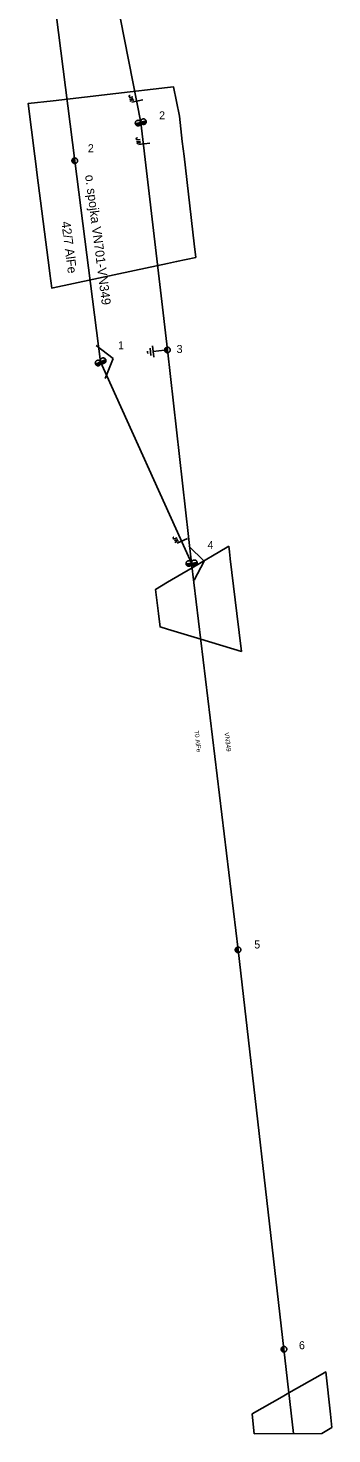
# Model space of a CAD drawing. Extents: x -536397 to -535454, y -1201642 to -1200953.
# Drawn here: x -536243 to -536176.6, y -1201641.8 to -1201334.5 of the extents above; entities that cross this region are included whole.
import ezdxf

# ---------------------------------------------------------------- set-up
doc = ezdxf.new("R2010")
doc.units = 0
for name, color, linetype in [('DOPLŇ_POPISY', 7, 'Continuous'), ('ELE_EON', 7, 'Continuous'), ('ELE_EON_POPIS', 7, 'Continuous'), ('KN_HRAN_POHYBLIVÁ', 7, 'Continuous'), ('PB_NN', 7, 'Continuous'), ('PB_NN_POPIS', 7, 'Continuous'), ('PK_HRAN_SPORNÁ', 7, 'Continuous'), ('PLG_EXPORT_GPE', 7, 'Continuous'), ('PODZEM_NN_POPIS', 7, 'Continuous'), ('RÁMEČEK', 7, 'Continuous'), ('SDEL_EON', 7, 'Continuous')]:
    doc.layers.add(name, color=color, linetype=linetype)

# ---------------------------------------------------------------- blocks, each defined once
blk = doc.blocks.new('VN840')
at = {"layer": 'RÁMEČEK'}
for points in [[(-0.01, 1.41), (-0.01, -1.09)], [(-1.51, -1.24), (-1.51, -1.15)], [(-1.48, -1.35), (-1.51, -1.24)], [(-1.33, -1.42), (-1.48, -1.35)], [(-1.27, -1.42), (-1.33, -1.42)], [(-1.13, -1.35), (-1.27, -1.42)], [(-1.09, -1.24), (-1.13, -1.35)], [(-1.09, -0.59), (-1.09, -1.24)], [(-0.68, -0.59), (-0.68, -1.42)], [(-0.68, -1.11), (-0.27, -0.59)], [(-0.54, -0.94), (-0.2, -1.42)]]:
    blk.add_lwpolyline(points, dxfattribs=at)
blk = doc.blocks.new('VN860')
at = {"layer": 'RÁMEČEK'}
for points in [[(-3.74, 0), (0.01, 2.82)], [(0.01, 2.82), (3.76, 0)]]:
    blk.add_lwpolyline(points, dxfattribs=at)
blk = doc.blocks.new('VN440')
at = {"layer": 'ELE_EON_POPIS'}
for points in [[(1.22, 0), (1.21, 0.13), (1.19, 0.25), (1.16, 0.38), (1.11, 0.5), (1.05, 0.61), (0.98, 0.72), (0.9, 0.82), (0.81, 0.91), (0.71, 0.99), (0.6, 1.06), (0.49, 1.12), (0.37, 1.16), (0.25, 1.2), (0.12, 1.22), (-0.01, 1.22), (-0.14, 1.22), (-0.26, 1.2), (-0.39, 1.16), (-0.51, 1.12), (-0.62, 1.06), (-0.73, 0.99), (-0.83, 0.91), (-0.92, 0.82), (-1, 0.72), (-1.07, 0.61), (-1.13, 0.5), (-1.18, 0.38), (-1.21, 0.25), (-1.23, 0.13), (-1.24, 0), (-1.23, -0.13), (-1.21, -0.26), (-1.18, -0.38), (-1.13, -0.5), (-1.07, -0.62), (-1, -0.73), (-0.92, -0.83), (-0.83, -0.92), (-0.73, -1), (-0.62, -1.07), (-0.51, -1.13), (-0.39, -1.17), (-0.26, -1.2), (-0.14, -1.23), (-0.01, -1.23), (0.12, -1.23), (0.25, -1.2), (0.37, -1.17), (0.49, -1.13), (0.6, -1.07), (0.71, -1), (0.81, -0.92), (0.9, -0.83), (0.98, -0.73), (1.05, -0.62), (1.11, -0.5), (1.16, -0.38), (1.19, -0.26), (1.21, -0.13), (1.22, 0)], [(-1.24, 0), (1.22, 0)], [(-1.18, -0.34), (1.1, -0.34)], [(-1.01, -0.63), (0.97, -0.63)], [(-0.74, -0.92), (0.68, -0.92)]]:
    blk.add_lwpolyline(points, dxfattribs=at)
blk = doc.blocks.new('VN810')
at = {"layer": 'PLG_EXPORT_GPE'}
for points in [[(0, -1.25), (0, -3.75)], [(1.25, -3.75), (-1.25, -3.75)], [(0.77, -4.37), (-0.8, -4.37)], [(0, -5), (-0.25, -5)], [(0.27, -5), (0, -5)]]:
    blk.add_lwpolyline(points, dxfattribs=at)
blk = doc.blocks.new('VN450')
at = {"layer": 'ELE_EON_POPIS'}
for points in [[(0, 0), (-0.01, 0.13), (-0.03, 0.25), (-0.06, 0.38), (-0.11, 0.5), (-0.16, 0.61), (-0.23, 0.72), (-0.31, 0.82), (-0.4, 0.91), (-0.5, 0.99), (-0.61, 1.06), (-0.72, 1.11), (-0.84, 1.16), (-0.97, 1.19), (-1.09, 1.21), (-1.22, 1.22), (-1.35, 1.21), (-1.47, 1.19), (-1.59, 1.16), (-1.71, 1.11), (-1.83, 1.06), (-1.93, 0.99), (-2.03, 0.91), (-2.12, 0.82), (-2.2, 0.72), (-2.27, 0.61), (-2.33, 0.5), (-2.38, 0.38), (-2.41, 0.25), (-2.43, 0.13), (-2.44, 0), (-2.43, -0.13), (-2.41, -0.25), (-2.38, -0.38), (-2.33, -0.5), (-2.27, -0.61), (-2.2, -0.72), (-2.12, -0.82), (-2.03, -0.91), (-1.93, -0.99), (-1.83, -1.06), (-1.71, -1.11), (-1.59, -1.16), (-1.47, -1.19), (-1.35, -1.21), (-1.22, -1.22), (-1.09, -1.21), (-0.97, -1.19), (-0.84, -1.16), (-0.72, -1.11), (-0.61, -1.06), (-0.5, -0.99), (-0.4, -0.91), (-0.31, -0.82), (-0.23, -0.72), (-0.16, -0.61), (-0.11, -0.5), (-0.06, -0.38), (-0.03, -0.25), (-0.01, -0.13), (0, 0)], [(-2.44, 0), (2.44, 0)], [(2.44, 0), (2.43, 0.13), (2.41, 0.25), (2.38, 0.38), (2.33, 0.5), (2.27, 0.61), (2.2, 0.72), (2.12, 0.82), (2.03, 0.91), (1.94, 0.99), (1.83, 1.06), (1.71, 1.11), (1.6, 1.16), (1.47, 1.19), (1.35, 1.21), (1.22, 1.22), (1.09, 1.21), (0.97, 1.19), (0.84, 1.16), (0.72, 1.11), (0.61, 1.06), (0.5, 0.99), (0.4, 0.91), (0.31, 0.82), (0.23, 0.72), (0.16, 0.61), (0.11, 0.5), (0.06, 0.38), (0.03, 0.25), (0.01, 0.13), (0, 0), (0.01, -0.13), (0.03, -0.25), (0.06, -0.38), (0.11, -0.5), (0.16, -0.61), (0.23, -0.72), (0.31, -0.82), (0.4, -0.91), (0.5, -0.99), (0.61, -1.06), (0.72, -1.11), (0.84, -1.16), (0.97, -1.19), (1.09, -1.21), (1.22, -1.22), (1.35, -1.21), (1.47, -1.19), (1.6, -1.16), (1.71, -1.11), (1.83, -1.06), (1.94, -0.99), (2.03, -0.91), (2.12, -0.82), (2.2, -0.72), (2.27, -0.61), (2.33, -0.5), (2.38, -0.38), (2.41, -0.25), (2.43, -0.13), (2.44, 0)], [(-2.4, -0.31), (-0.04, -0.31)], [(-2.26, -0.61), (-0.17, -0.61)], [(-2.01, -0.92), (-0.42, -0.92)], [(0.04, -0.31), (2.4, -0.31)], [(0.17, -0.61), (2.27, -0.61)], [(0.42, -0.92), (2.02, -0.92)]]:
    blk.add_lwpolyline(points, dxfattribs=at)

msp = doc.modelspace()

# ---------------------------------------------------------------- linework, layer by layer
at = {"layer": 'ELE_EON'}
for points in [[(-536229.86, -1201296.57), (-536218.36, -1201355.13), (-536212.54, -1201404.88), (-536207.27, -1201451.49)], [(-536207.27, -1201451.49), (-536197.12, -1201536.02), (-536187.09, -1201623.35), (-536185.03, -1201641.79)]]:
    msp.add_lwpolyline(points, dxfattribs=at)
at = {"layer": 'PK_HRAN_SPORNÁ'}
for points in [[(-536223.8, -1201348.8), (-536212.5, -1201347.49), (-536211.24, -1201347.33), (-536209.94, -1201353.78), (-536209.3, -1201359.3), (-536208.92, -1201362.5), (-536206.69, -1201381.69), (-536206.34, -1201384.65), (-536210.55, -1201385.55), (-536212.5, -1201385.96), (-536219.72, -1201387.5), (-536237.5, -1201391.29), (-536237.79, -1201391.34), (-536238.2, -1201388.2), (-536238.29, -1201387.5), (-536241.06, -1201366.06), (-536241.22, -1201364.8), (-536241.51, -1201362.5), (-536242.96, -1201351.03), (-536237.5, -1201350.39)], [(-536199.14, -1201447.78), (-536199, -1201449), (-536198.83, -1201450.48), (-536198.83, -1201450.51), (-536198.82, -1201450.53), (-536197.38, -1201462.5), (-536196.39, -1201470.78), (-536205.28, -1201468.1), (-536212.5, -1201465.93), (-536214.16, -1201465.43), (-536214.3, -1201464.3), (-536214.51, -1201462.5), (-536215.14, -1201457.24), (-536212.5, -1201455.68), (-536207.15, -1201452.51), (-536199.52, -1201448.01)], [(-536193.58, -1201641.85), (-536194.07, -1201637.5), (-536194.07, -1201637.47), (-536187.5, -1201633.73), (-536186.03, -1201632.89), (-536178.71, -1201628.71), (-536177.98, -1201628.3), (-536176.96, -1201637.5), (-536176.63, -1201640.42), (-536178.82, -1201641.75)]]:
    msp.add_lwpolyline(points, close=True, dxfattribs=at)
at = {"layer": 'PODZEM_NN_POPIS'}
msp.add_lwpolyline([(-536238.86, -1201315.34), (-536232.78, -1201363.5), (-536227.13, -1201407.48), (-536207.27, -1201451.49)], dxfattribs=at)

# ---------------------------------------------------------------- block references
at = {"layer": 'DOPLŇ_POPISY'}
for name, p, xscale, yscale, rotation in [('VN450', (-536218.36, -1201355.13), 0.4999999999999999, 0.49999999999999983, 14.6363055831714), ('VN440', (-536232.78, -1201363.51), 0.5000000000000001, 0.5, -82.79528052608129), ('VN440', (-536212.54, -1201404.88), 0.5, 0.5000000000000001, -83.35179166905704), ('VN450', (-536227.13, -1201407.48), 0.5, 0.5, 24.700652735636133), ('VN450', (-536207.27, -1201451.49), 0.5, 0.5, 7.6230417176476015), ('VN440', (-536197.12, -1201536.02), 0.5000000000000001, 0.5, -83.15304168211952), ('VN440', (-536187.09, -1201623.35), 0.5, 0.5, -83.44827777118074)]:
    msp.add_blockref(name, p, dxfattribs=dict(at, xscale=xscale, yscale=yscale, rotation=rotation))
at = {"layer": 'KN_HRAN_POHYBLIVÁ'}
for name, p, rotation in [('VN840', (-536219.28, -1201350.48), -78.58695282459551), ('VN840', (-536217.78, -1201359.88), -83.35163336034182), ('VN860', (-536227.13, -1201407.48), -74.68854724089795), ('VN840', (-536209.44, -1201446.68), -65.71219719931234), ('VN860', (-536207.27, -1201451.49), -81.0083778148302)]:
    msp.add_blockref(name, p, dxfattribs=dict(at, rotation=rotation))
at = {"layer": 'RÁMEČEK', "rotation": -83.35240554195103}
msp.add_blockref('VN810', (-536211.91, -1201404.8), dxfattribs=at)

# ---------------------------------------------------------------- texts
at = {"layer": 'ELE_EON_POPIS'}
msp.add_text('70 AlFe', height=1, rotation=276.847, dxfattribs=at).set_placement((-536206.69, -1201488.14))
at = {"layer": 'PB_NN'}
msp.add_text('42/7 AlFe', height=2, rotation=277.37, dxfattribs=at).set_placement((-536235.72, -1201376.89))
at = {"layer": 'PB_NN_POPIS'}
msp.add_text('o. spojka VN701-VN349', height=2, rotation=277.37, dxfattribs=at).set_placement((-536230.52, -1201366.7))
at = {"layer": 'PLG_EXPORT_GPE'}
for s, p in [('2', (-536214.36, -1201354.47)), ('2', (-536229.92, -1201361.65)), ('1', (-536223.33, -1201404.74)), ('3', (-536210.54, -1201405.54)), ('4', (-536203.79, -1201448.39)), ('5', (-536193.58, -1201535.73)), ('6', (-536183.82, -1201623.34))]:
    msp.add_text(s, height=1.75, dxfattribs=at).set_placement(p)
at = {"layer": 'SDEL_EON'}
msp.add_text('VN349', height=1, rotation=276.847, dxfattribs=at).set_placement((-536200.1, -1201488.54))

doc.saveas('drawing.dxf')
